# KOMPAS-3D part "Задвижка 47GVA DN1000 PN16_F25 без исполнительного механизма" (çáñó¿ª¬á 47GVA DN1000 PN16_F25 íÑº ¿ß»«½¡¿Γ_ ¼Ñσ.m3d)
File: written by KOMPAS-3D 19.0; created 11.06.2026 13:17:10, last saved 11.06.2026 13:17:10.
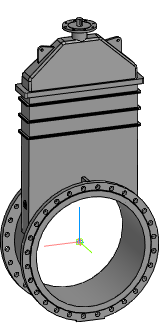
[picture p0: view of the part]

Document properties: Автор: Евгений; Полное имя файла: Z:\3.Личные\kachalov\001_3d для проектировщиков\2.2 Тип 47GVA, 47GVA.Z\_stp\_stp_Задвижка 47GVA DN40-DN1000 без исп.мех\Задвижка 47GVA DN1000 PN16_F25 без исполнит_ мех.m3d

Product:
- Part/product: Задвижка 47GVA DN1000 PN16_F25 без исполнительного механизма

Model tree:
1. Операция без истории:1  (labels: Задвижка 47GVA DN1000 PN16_F25 без исполнительного механизма)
